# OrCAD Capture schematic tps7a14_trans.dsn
size A
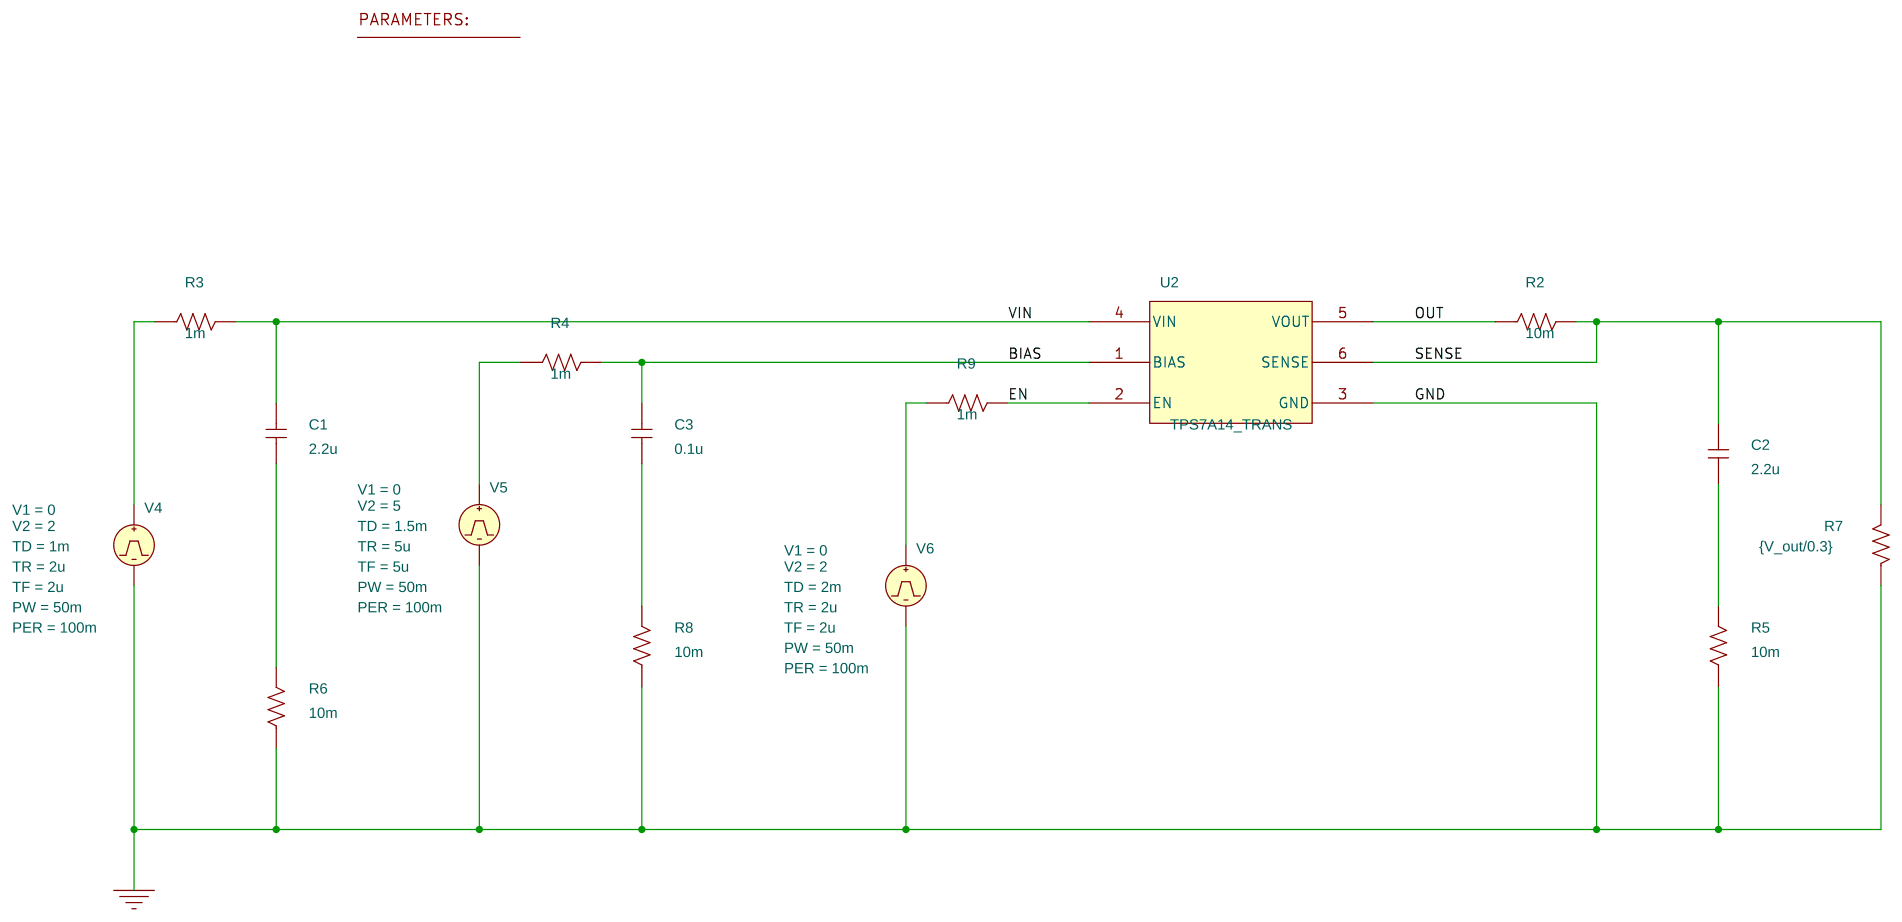
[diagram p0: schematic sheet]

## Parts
1  PARAM
C1  2.2u  [cap196]
C2  2.2u  [cap196]
C3  0.1u  [cap196]
R2  10m  [AXRC05]
R3  1m  [AXRC05]
R4  1m  [AXRC05]
R5  10m  [AXRC05]
R6  10m  [AXRC05]
R7  {V_out/0.3}  [AXRC05]
R8  10m  [AXRC05]
R9  1m  [AXRC05]
U2  TPS7A14_TRANS
V4  VPULSE
V5  VPULSE
V6  VPULSE

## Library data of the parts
1 = PARAM: V_out: 0.8
C1-C3 = C
R2-R9 = R
U2 = TPS7A14_TRANS_2
V4 = VPULSE: PER: 100m; PW: 50m; TD: 1m; TF: 2u; TR: 2u; V1: 0; V2: 2
V5 = VPULSE: PER: 100m; PW: 50m; TD: 1.5m; TF: 5u; TR: 5u; V1: 0; V2: 5
V6 = VPULSE: PER: 100m; PW: 50m; TD: 2m; TF: 2u; TR: 2u; V1: 0; V2: 2

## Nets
VIN: C1.2 R3.2 U2.4(VIN)
0: R5.1 R6.1 R7.1 R8.1 U2.3(GND) V4.2(-) V5.2(-) V6.2(-)
BIAS: C3.2 R4.2 U2.1(BIAS)
EN: R9.2 U2.2(EN)
OUT: R2.1 U2.5(VOUT)
SENSE: C2.2 R2.2 R7.2 U2.6(SENSE)
N00241: R3.1 V4.1(+)
N06623: R4.1 V5.1(+)
N07169: C2.1 R5.2
N08018: C1.1 R6.2
N09513: C3.1 R8.2
N11090: R9.1 V6.1(+)
